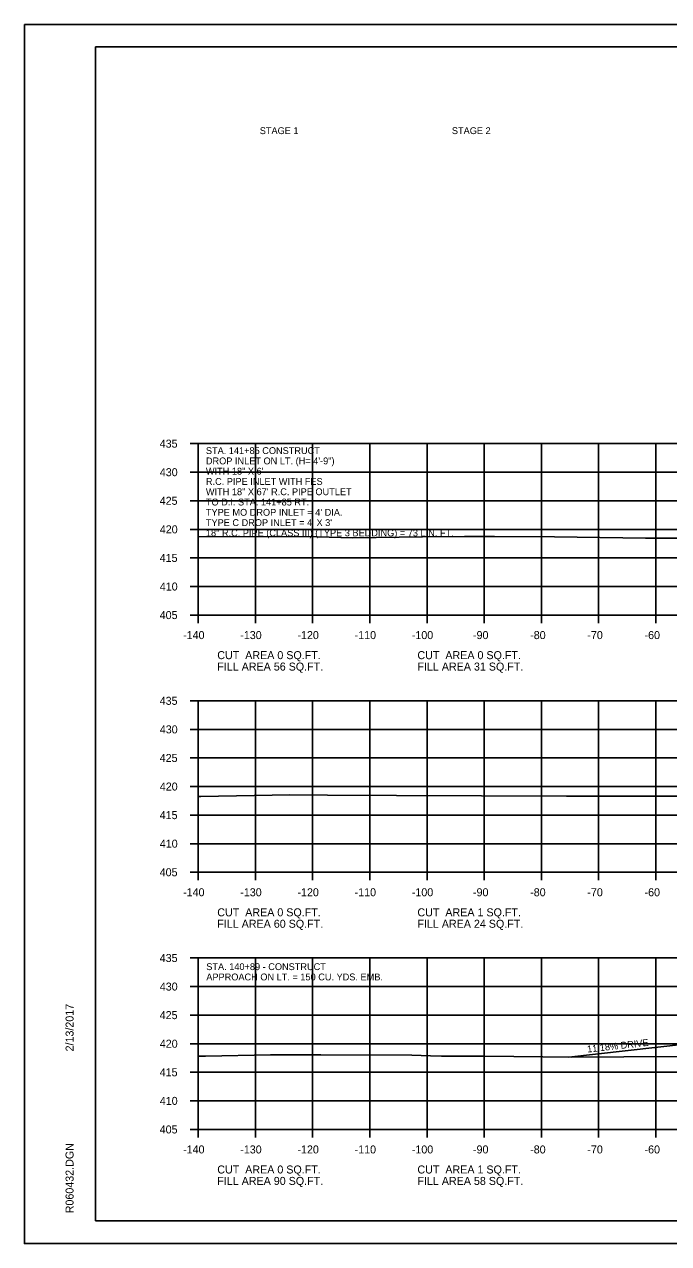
# Model space of a CAD drawing. Extents: x 1538688 to 1540766, y 656250 to 671912.
# Drawn here: x 1538687.8 to 1538800.4, y 662311.4 to 662524.7 of the extents above; entities that cross this region are included whole.
import ezdxf

# ---------------------------------------------------------------- set-up
doc = ezdxf.new("R2010")
doc.units = 0
for name, color, linetype in [('16', 7, 'Continuous'), ('18', 7, 'Continuous'), ('22', 7, 'Continuous'), ('26', 7, 'Continuous'), ('40', 7, 'Continuous'), ('7', 7, 'Continuous'), ('Borings', 7, 'Continuous'), ('Default', 7, 'Continuous'), ('Horizontal Alignment', 7, 'Continuous'), ('RipRap', 7, 'Continuous')]:
    doc.layers.add(name, color=color, linetype=linetype)

msp = doc.modelspace()

# ---------------------------------------------------------------- linework, layer by layer
at = {"layer": '16'}
msp.add_line((1538783, 662343.98), (1538803.2, 662346.24), dxfattribs=at)
at = {"layer": '18'}
for points in [[(1538718.18, 662435.1), (1538738.98, 662435.06), (1538745.22, 662434.87), (1538757.41, 662435.06), (1538764.71, 662435.08), (1538770.01, 662435.1), (1538780.45, 662435.05), (1538796.37, 662434.8), (1538798.02, 662434.8), (1538805.25, 662434.79)], [(1538718.18, 662389.61), (1538718.62, 662389.62), (1538734.2, 662389.9), (1538740.79, 662389.83), (1538752.87, 662389.77), (1538782.56, 662389.66), (1538804.11, 662389.63)], [(1538718.18, 662344.16), (1538719.44, 662344.18), (1538730.81, 662344.38), (1538739.6, 662344.4), (1538755.5, 662344.34), (1538758.81, 662344.23), (1538760.72, 662344.18), (1538768.27, 662344.17), (1538783.51, 662343.96), (1538783.53, 662343.96), (1538792.62, 662344.05), (1538807.07, 662344.1)]]:
    msp.add_lwpolyline(points, dxfattribs=at)
at = {"layer": '22'}
for p, q in [((1538718.18, 662451.34), (1538998.18, 662451.34)), ((1538718.18, 662421.34), (1538718.18, 662451.34)), ((1538728.18, 662421.34), (1538728.18, 662451.34)), ((1538738.18, 662421.34), (1538738.18, 662451.34)), ((1538748.18, 662421.34), (1538748.18, 662451.34)), ((1538758.18, 662421.34), (1538758.18, 662451.34)), ((1538768.18, 662421.34), (1538768.18, 662451.34)), ((1538778.18, 662421.34), (1538778.18, 662451.34)), ((1538788.18, 662421.34), (1538788.18, 662451.34)), ((1538798.18, 662421.34), (1538798.18, 662451.34)), ((1538718.18, 662446.34), (1538998.18, 662446.34)), ((1538718.18, 662441.34), (1538998.18, 662441.34)), ((1538718.18, 662436.34), (1538998.18, 662436.34)), ((1538718.18, 662431.34), (1538998.18, 662431.34)), ((1538718.18, 662426.34), (1538998.18, 662426.34)), ((1538718.18, 662421.34), (1538998.18, 662421.34)), ((1538718.18, 662406.34), (1538998.18, 662406.34)), ((1538718.18, 662376.34), (1538718.18, 662406.34)), ((1538728.18, 662376.34), (1538728.18, 662406.34)), ((1538738.18, 662376.34), (1538738.18, 662406.34)), ((1538748.18, 662376.34), (1538748.18, 662406.34)), ((1538758.18, 662376.34), (1538758.18, 662406.34)), ((1538768.18, 662376.34), (1538768.18, 662406.34)), ((1538778.18, 662376.34), (1538778.18, 662406.34)), ((1538788.18, 662376.34), (1538788.18, 662406.34)), ((1538798.18, 662376.34), (1538798.18, 662406.34)), ((1538718.18, 662401.34), (1538998.18, 662401.34)), ((1538718.18, 662396.34), (1538998.18, 662396.34)), ((1538718.18, 662391.34), (1538998.18, 662391.34)), ((1538718.18, 662386.34), (1538998.18, 662386.34)), ((1538718.18, 662381.34), (1538998.18, 662381.34)), ((1538718.18, 662376.34), (1538998.18, 662376.34)), ((1538718.18, 662361.34), (1538998.18, 662361.34)), ((1538718.18, 662331.34), (1538718.18, 662361.34)), ((1538728.18, 662331.34), (1538728.18, 662361.34)), ((1538738.18, 662331.34), (1538738.18, 662361.34)), ((1538748.18, 662331.34), (1538748.18, 662361.34)), ((1538758.18, 662331.34), (1538758.18, 662361.34)), ((1538768.18, 662331.34), (1538768.18, 662361.34)), ((1538778.18, 662331.34), (1538778.18, 662361.34)), ((1538788.18, 662331.34), (1538788.18, 662361.34)), ((1538798.18, 662331.34), (1538798.18, 662361.34)), ((1538718.18, 662356.34), (1538998.18, 662356.34)), ((1538718.18, 662351.34), (1538998.18, 662351.34)), ((1538718.18, 662346.34), (1538998.18, 662346.34)), ((1538718.18, 662341.34), (1538998.18, 662341.34)), ((1538718.18, 662336.34), (1538998.18, 662336.34)), ((1538718.18, 662331.34), (1538998.18, 662331.34))]:
    msp.add_line(p, q, dxfattribs=at)
at = {"layer": '26'}
for p, q in [((1538687.78, 662524.7), (1539021.11, 662524.7)), ((1538687.78, 662311.37), (1539021.11, 662311.37))]:
    msp.add_line(p, q, dxfattribs=at)
msp.add_lwpolyline([(1538687.77, 662524.7), (1539021.11, 662524.7), (1539021.11, 662311.36), (1538687.77, 662311.36)], close=True, dxfattribs=at)
at = {"layer": 'Borings'}
for p, q in [((1538716.78, 662451.34), (1538718.18, 662451.34)), ((1538718.18, 662421.34), (1538718.18, 662451.34)), ((1538716.78, 662446.34), (1538718.18, 662446.34)), ((1538716.78, 662441.34), (1538718.18, 662441.34)), ((1538716.78, 662436.34), (1538718.18, 662436.34)), ((1538716.78, 662431.34), (1538718.18, 662431.34)), ((1538716.78, 662426.34), (1538718.18, 662426.34)), ((1538716.78, 662421.34), (1538718.18, 662421.34)), ((1538718.18, 662421.34), (1538998.18, 662421.34)), ((1538718.18, 662419.94), (1538718.18, 662421.34)), ((1538728.18, 662419.94), (1538728.18, 662421.34)), ((1538738.18, 662419.94), (1538738.18, 662421.34)), ((1538748.18, 662419.94), (1538748.18, 662421.34)), ((1538758.18, 662419.94), (1538758.18, 662421.34)), ((1538768.18, 662419.94), (1538768.18, 662421.34)), ((1538778.18, 662419.94), (1538778.18, 662421.34)), ((1538788.18, 662419.94), (1538788.18, 662421.34)), ((1538798.18, 662419.94), (1538798.18, 662421.34)), ((1538716.78, 662406.34), (1538718.18, 662406.34)), ((1538718.18, 662376.34), (1538718.18, 662406.34)), ((1538716.78, 662401.34), (1538718.18, 662401.34)), ((1538716.78, 662396.34), (1538718.18, 662396.34)), ((1538716.78, 662391.34), (1538718.18, 662391.34)), ((1538716.78, 662386.34), (1538718.18, 662386.34)), ((1538716.78, 662381.34), (1538718.18, 662381.34)), ((1538716.78, 662376.34), (1538718.18, 662376.34)), ((1538718.18, 662376.34), (1538998.18, 662376.34)), ((1538718.18, 662374.94), (1538718.18, 662376.34)), ((1538728.18, 662374.94), (1538728.18, 662376.34)), ((1538738.18, 662374.94), (1538738.18, 662376.34)), ((1538748.18, 662374.94), (1538748.18, 662376.34)), ((1538758.18, 662374.94), (1538758.18, 662376.34)), ((1538768.18, 662374.94), (1538768.18, 662376.34)), ((1538778.18, 662374.94), (1538778.18, 662376.34)), ((1538788.18, 662374.94), (1538788.18, 662376.34)), ((1538798.18, 662374.94), (1538798.18, 662376.34)), ((1538716.78, 662361.34), (1538718.18, 662361.34)), ((1538718.18, 662331.34), (1538718.18, 662361.34)), ((1538716.78, 662356.34), (1538718.18, 662356.34)), ((1538716.78, 662351.34), (1538718.18, 662351.34)), ((1538716.78, 662346.34), (1538718.18, 662346.34)), ((1538716.78, 662341.34), (1538718.18, 662341.34)), ((1538716.78, 662336.34), (1538718.18, 662336.34)), ((1538716.78, 662331.34), (1538718.18, 662331.34)), ((1538718.18, 662331.34), (1538998.18, 662331.34)), ((1538718.18, 662329.94), (1538718.18, 662331.34)), ((1538728.18, 662329.94), (1538728.18, 662331.34)), ((1538738.18, 662329.94), (1538738.18, 662331.34)), ((1538748.18, 662329.94), (1538748.18, 662331.34)), ((1538758.18, 662329.94), (1538758.18, 662331.34)), ((1538768.18, 662329.94), (1538768.18, 662331.34)), ((1538778.18, 662329.94), (1538778.18, 662331.34)), ((1538788.18, 662329.94), (1538788.18, 662331.34)), ((1538798.18, 662329.94), (1538798.18, 662331.34))]:
    msp.add_line(p, q, dxfattribs=at)
at = {"layer": 'RipRap'}
for p, q in [((1538700.18, 662520.8), (1539016.36, 662520.8)), ((1538700.18, 662315.34), (1538700.18, 662520.8)), ((1538700.18, 662315.34), (1538700.18, 662315.34)), ((1539016.36, 662315.34), (1538700.18, 662315.34))]:
    msp.add_line(p, q, dxfattribs=at)

# ---------------------------------------------------------------- texts
at = {"layer": '16'}
msp.add_text('11.18% DRIVE', height=1.2, rotation=6.3793, dxfattribs=at).set_placement((1538786.25, 662344.78))
at = {"layer": '40'}
for s, p in [('STA. 141+85 CONSTRUCT', (1538719.51, 662449.52)), ('DROP INLET ON LT. (H= 4\'-9")', (1538719.51, 662447.72)), ('WITH 18" X 6\'', (1538719.51, 662445.92)), ('R.C. PIPE INLET WITH FES ', (1538719.51, 662444.12)), ('WITH 18" X 67\' R.C. PIPE OUTLET', (1538719.51, 662442.32)), ('TO D.I. STA. 141+85 RT.', (1538719.51, 662440.52)), ("TYPE MO DROP INLET = 4' DIA.", (1538719.51, 662438.72)), ("TYPE C DROP INLET = 4' X 3'", (1538719.51, 662436.92)), ('18" R.C. PIPE (CLASS III) (TYPE 3 BEDDING) = 73 LIN. FT.', (1538719.51, 662435.12))]:
    msp.add_text(s, height=1.2, dxfattribs=at).set_placement(p)
at = {"layer": '7'}
for s, p in [('STA. 140+89 - CONSTRUCT', (1538719.58, 662359.22)), ('APPROACH ON LT. = 150 CU. YDS. EMB.', (1538719.58, 662357.42))]:
    msp.add_text(s, height=1.2, dxfattribs=at).set_placement(p)
at = {"layer": 'Default'}
for s, p in [('STAGE 1', (1538728.93, 662505.5)), ('STAGE 2', (1538762.53, 662505.5))]:
    msp.add_text(s, height=1.2, dxfattribs=at).set_placement(p)
at = {"layer": 'Horizontal Alignment'}
for s, p in [('435', (1538711.43, 662450.64)), ('430', (1538711.45, 662445.64)), ('425', (1538711.43, 662440.64)), ('420', (1538711.45, 662435.64)), ('415', (1538711.43, 662430.64)), ('410', (1538711.45, 662425.64)), ('405', (1538711.43, 662420.64)), ('-140', (1538715.52, 662417.14)), ('-130', (1538725.52, 662417.14)), ('-120', (1538735.52, 662417.14)), ('-110', (1538745.52, 662417.14)), ('-100', (1538755.52, 662417.14)), ('-90', (1538766.22, 662417.14)), ('-80', (1538776.22, 662417.14)), ('-70', (1538786.22, 662417.14)), ('-60', (1538796.22, 662417.14)), ('CUT  AREA 0 SQ.FT.', (1538721.5, 662413.63)), ('CUT  AREA 0 SQ.FT.', (1538756.5, 662413.63)), ('FILL AREA 56 SQ.FT.', (1538721.5, 662411.63)), ('FILL AREA 31 SQ.FT.', (1538756.5, 662411.63)), ('435', (1538711.43, 662405.64)), ('430', (1538711.45, 662400.64)), ('425', (1538711.43, 662395.64)), ('420', (1538711.45, 662390.64)), ('415', (1538711.43, 662385.64)), ('410', (1538711.45, 662380.64)), ('405', (1538711.43, 662375.64)), ('-140', (1538715.52, 662372.14)), ('-130', (1538725.52, 662372.14)), ('-120', (1538735.52, 662372.14)), ('-110', (1538745.52, 662372.14)), ('-100', (1538755.52, 662372.14)), ('-90', (1538766.22, 662372.14)), ('-80', (1538776.22, 662372.14)), ('-70', (1538786.22, 662372.14)), ('-60', (1538796.22, 662372.14)), ('CUT  AREA 0 SQ.FT.', (1538721.5, 662368.63)), ('CUT  AREA 1 SQ.FT.', (1538756.5, 662368.63)), ('FILL AREA 60 SQ.FT.', (1538721.5, 662366.63)), ('FILL AREA 24 SQ.FT.', (1538756.5, 662366.63)), ('435', (1538711.43, 662360.64)), ('430', (1538711.45, 662355.64)), ('425', (1538711.43, 662350.64)), ('420', (1538711.45, 662345.64)), ('415', (1538711.43, 662340.64)), ('410', (1538711.45, 662335.64)), ('405', (1538711.43, 662330.64)), ('-140', (1538715.52, 662327.14)), ('-130', (1538725.52, 662327.14)), ('-120', (1538735.52, 662327.14)), ('-110', (1538745.52, 662327.14)), ('-100', (1538755.52, 662327.14)), ('-90', (1538766.22, 662327.14)), ('-80', (1538776.22, 662327.14)), ('-70', (1538786.22, 662327.14)), ('-60', (1538796.22, 662327.14)), ('CUT  AREA 0 SQ.FT.', (1538721.5, 662323.63)), ('CUT  AREA 1 SQ.FT.', (1538756.5, 662323.63)), ('FILL AREA 90 SQ.FT.', (1538721.5, 662321.63)), ('FILL AREA 58 SQ.FT.', (1538756.5, 662321.63))]:
    msp.add_text(s, height=1.4, dxfattribs=at).set_placement(p)
at = {"layer": 'RipRap'}
for s, p in [('2/13/2017', (1538696.37, 662344.99)), ('R060432.DGN', (1538696.37, 662316.67))]:
    msp.add_text(s, height=1.4, rotation=90, dxfattribs=at).set_placement(p)

doc.saveas('drawing.dxf')
